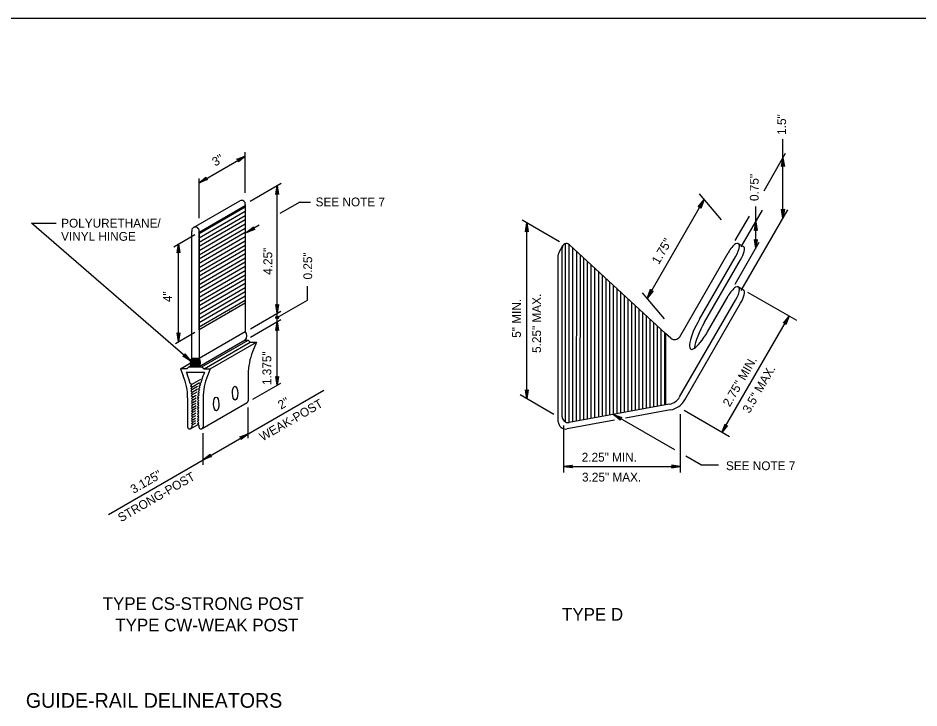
# Model space of a CAD drawing. Extents: x 640253 to 641999, y 298458 to 299646.
# Drawn here: x 640490.1 to 640796.8, y 298801.7 to 299036.6 of the extents above; entities that cross this region are included whole.
import ezdxf

# ---------------------------------------------------------------- set-up
doc = ezdxf.new("R2010")
doc.units = 0
doc.layers.add('1', color=7, linetype='Continuous')
doc.layers.add('2', color=7, linetype='Continuous')

msp = doc.modelspace()

# ---------------------------------------------------------------- linework, layer by layer
at = {"layer": '1'}
msp.add_line((640293.31, 299036.63), (641079.31, 299036.63), dxfattribs=at)
at = {"layer": '2'}
for p, q in [((640750.54, 298968.53), (640750.54, 298995.34)), ((640567.51, 298977.15), (640567.51, 298990.93)), ((640744.09, 298977.84), (640751.44, 298990.57)), ((640551.76, 298980.53), (640567.51, 298989.62)), ((640551.76, 298968.46), (640551.76, 298982)), ((640569.19, 298974.27), (640579.72, 298980.35)), ((640578.36, 298936.09), (640578.36, 298979.57)), ((640704.26, 298941.18), (640723.7, 298974.85)), ((640729.66, 298967.89), (640722.11, 298976.71)), ((640549.88, 298965.29), (640565.62, 298974.38)), ((640551.76, 298963.24), (640567.51, 298972.33)), ((640567.51, 298973.08), (640567.51, 298929.88)), ((640586.04, 298973.92), (640579.26, 298970.05)), ((640586.04, 298973.92), (640589.7, 298973.92)), ((640741.28, 298967.28), (640741.28, 298972.5)), ((640551.76, 298961.8), (640567.51, 298970.89)), ((640551.76, 298960.36), (640567.51, 298969.44)), ((640734.29, 298960.88), (640739.09, 298969.18)), ((640736.28, 298943.84), (640752.15, 298971.31)), ((640736.31, 298958.67), (640743.57, 298971.24)), ((640494.74, 298966.76), (640503.1, 298966.76)), ((640548.82, 298919.89), (640494.74, 298966.76)), ((640551.76, 298958.91), (640567.51, 298968)), ((640551.76, 298957.47), (640567.51, 298966.56)), ((640572.24, 298966.05), (640567.94, 298963.59)), ((640674.43, 298960.44), (640661.77, 298967.76)), ((640663.36, 298907.01), (640663.36, 298966.84)), ((640741.28, 298958.24), (640741.28, 298967.28)), ((640543.17, 298958.76), (640550.37, 298962.92)), ((640549.27, 298920.78), (640549.27, 298963.99)), ((640551.76, 298956.02), (640567.51, 298965.11)), ((640551.76, 298963.99), (640551.76, 298920.78)), ((640551.76, 298963.46), (640551.99, 298963.86)), ((640551.76, 298963.5), (640551.96, 298963.84)), ((640551.76, 298954.58), (640567.51, 298963.67)), ((640551.76, 298953.14), (640567.51, 298962.23)), ((640544.78, 298926.43), (640544.78, 298959.7)), ((640551.76, 298951.7), (640567.51, 298960.78)), ((640551.76, 298950.25), (640567.51, 298959.34)), ((640674.3, 298956.85), (640675.62, 298959.13)), ((640676.55, 298899.06), (640676.56, 298959.77)), ((640677.8, 298898.91), (640677.8, 298959.48)), ((640695.7, 298942.98), (640677.87, 298959.44)), ((640677.9, 298959.42), (640710.55, 298929.26)), ((640734.24, 298946.06), (640742.46, 298960.28)), ((640735.34, 298959.83), (640737.1, 298958.82)), ((640551.76, 298948.81), (640567.51, 298957.9)), ((640551.76, 298947.36), (640567.51, 298956.45)), ((640674.06, 298899.19), (640674.06, 298956.04)), ((640675.38, 298900.87), (640675.38, 298958.32)), ((640679.05, 298899.14), (640679.05, 298958.35)), ((640680.3, 298899.37), (640680.31, 298957.2)), ((640681.55, 298899.6), (640681.56, 298956.04)), ((640715.38, 298928.12), (640731.89, 298956.72)), ((640551.76, 298945.92), (640567.51, 298955.01)), ((640551.76, 298944.48), (640567.51, 298953.57)), ((640682.8, 298899.83), (640682.8, 298954.89)), ((640684.05, 298900.06), (640684.05, 298953.73)), ((640722.09, 298934.05), (640734.39, 298955.34)), ((640723.82, 298933.05), (640736.12, 298954.34)), ((640551.76, 298943.03), (640567.51, 298952.12)), ((640551.76, 298941.59), (640567.51, 298950.68)), ((640685.3, 298900.29), (640685.3, 298952.58)), ((640686.55, 298900.52), (640686.55, 298951.42)), ((640687.8, 298900.75), (640687.8, 298950.27)), ((640551.76, 298940.15), (640567.51, 298949.24)), ((640551.76, 298938.7), (640567.51, 298947.79)), ((640689.05, 298900.98), (640689.05, 298949.12)), ((640690.3, 298901.2), (640690.3, 298947.96)), ((640691.55, 298901.43), (640691.55, 298946.81)), ((640551.76, 298937.26), (640567.51, 298946.35)), ((640551.76, 298935.82), (640567.51, 298944.91)), ((640588.68, 298940.61), (640588.68, 298945.31)), ((640692.8, 298901.66), (640692.8, 298945.65)), ((640694.05, 298901.89), (640694.06, 298944.5)), ((640735.35, 298945.09), (640737.12, 298944.07)), ((640551.76, 298934.37), (640567.51, 298943.46)), ((640551.76, 298932.93), (640567.51, 298942.02)), ((640695.3, 298902.12), (640695.3, 298943.35)), ((640696.55, 298902.35), (640696.55, 298942.19)), ((640697.8, 298902.58), (640697.8, 298941.04)), ((640710.22, 298934.23), (640702.67, 298943.04)), ((640724.85, 298929.79), (640731.87, 298941.95)), ((640755.23, 298933.62), (640738.62, 298943.2)), ((640551.76, 298931.49), (640567.51, 298940.58)), ((640578.36, 298934.65), (640588.68, 298940.61)), ((640699.05, 298902.81), (640699.05, 298939.88)), ((640700.3, 298903.04), (640700.3, 298938.73)), ((640715.35, 298907.59), (640734.39, 298940.55)), ((640717.08, 298906.59), (640736.12, 298939.55)), ((640562.12, 298936.44), (640562.43, 298936.96)), ((640569.22, 298930.82), (640579.61, 298936.81)), ((640578.36, 298933.2), (640578.36, 298936.09)), ((640701.55, 298903.27), (640701.55, 298937.57)), ((640702.8, 298903.5), (640702.8, 298936.42)), ((640704.05, 298903.73), (640704.05, 298935.27)), ((640729.75, 298895.51), (640752.63, 298935.12)), ((640569.22, 298927.93), (640579.61, 298933.93)), ((640578.36, 298911.57), (640578.36, 298933.2)), ((640705.3, 298903.96), (640705.3, 298934.11)), ((640706.55, 298904.19), (640706.55, 298932.96)), ((640707.8, 298904.41), (640707.8, 298931.8)), ((640543.72, 298925.81), (640550.3, 298929.61)), ((640551.76, 298920.78), (640567.51, 298929.88)), ((640709.05, 298904.64), (640709.05, 298930.65)), ((640710.3, 298904.87), (640710.3, 298929.5)), ((640712.37, 298927.59), (640710.55, 298929.26)), ((640710.55, 298929.26), (640710.55, 298904.92)), ((640567.51, 298926.99), (640551.76, 298917.9)), ((640552.74, 298917.9), (640568.49, 298926.99)), ((640553.45, 298917.19), (640569.2, 298926.28)), ((640555.6, 298917.19), (640571.35, 298926.28)), ((640567.51, 298926.99), (640568.49, 298926.99)), ((640568.49, 298926.99), (640569.2, 298926.28)), ((640569.2, 298926.28), (640571.35, 298926.28)), ((640571.35, 298926.28), (640570.01, 298923.02)), ((640548.77, 298919.45), (640550.11, 298920.78)), ((640548.79, 298919.12), (640550.46, 298920.78)), ((640548.84, 298918.82), (640550.81, 298920.78)), ((640548.85, 298919.89), (640549.75, 298920.78)), ((640548.92, 298918.54), (640551.17, 298920.78)), ((640549.01, 298918.28), (640551.52, 298920.78)), ((640549.07, 298920.46), (640549.4, 298920.78)), ((640549.15, 298918.06), (640551.81, 298920.72)), ((640549.27, 298920.78), (640551.76, 298920.78)), ((640549.34, 298917.9), (640551.95, 298920.51)), ((640549.69, 298917.9), (640552.08, 298920.28)), ((640550.04, 298917.9), (640552.16, 298920.01)), ((640550.4, 298917.9), (640552.23, 298919.73)), ((640550.75, 298917.9), (640552.27, 298919.41)), ((640545.43, 298917.19), (640548.77, 298919.11)), ((640547.58, 298917.19), (640545.43, 298917.19)), ((640545.43, 298917.19), (640546.4, 298914.83)), ((640548.29, 298917.9), (640547.58, 298917.19)), ((640548.29, 298917.9), (640549, 298918.31)), ((640548.29, 298917.9), (640552.74, 298917.9)), ((640551.1, 298917.9), (640552.24, 298919.03)), ((640551.46, 298917.9), (640552.13, 298918.57)), ((640551.76, 298917.9), (640551.77, 298917.9)), ((640552.74, 298917.9), (640553.45, 298917.19)), ((640553.45, 298917.19), (640555.6, 298917.19)), ((640555.6, 298917.19), (640554.63, 298914.83)), ((640547.42, 298916.07), (640553.61, 298916.07)), ((640547.42, 298916.07), (640547.68, 298915.43)), ((640549.22, 298911.82), (640552.36, 298913.63)), ((640553.61, 298916.07), (640553.34, 298915.42)), ((640568.51, 298915.36), (640568.51, 298906.3)), ((640549.2, 298911.84), (640548.72, 298912.18)), ((640549.22, 298911.82), (640548.81, 298911.24)), ((640549.25, 298910.94), (640548.81, 298911.24)), ((640549.25, 298910.94), (640548.93, 298910.49)), ((640549.35, 298910.13), (640548.93, 298910.49)), ((640549.35, 298910.13), (640548.96, 298909.68)), ((640549.25, 298910.94), (640551.95, 298912.5)), ((640549.35, 298910.13), (640551.26, 298911.23)), ((640549.45, 298909.26), (640551.29, 298910.32)), ((640551.54, 298910.33), (640552.06, 298910.78)), ((640551.54, 298910.33), (640551.93, 298909.88)), ((640551.71, 298911.27), (640552.21, 298911.62)), ((640551.71, 298911.27), (640552.06, 298910.78)), ((640551.86, 298912.11), (640552.38, 298912.47)), ((640551.86, 298912.11), (640552.21, 298911.62)), ((640570.1, 298906.8), (640579.61, 298912.29)), ((640520.9, 298867.59), (640594.28, 298909.95)), ((640547.88, 298907.26), (640547.88, 298897.42)), ((640549.45, 298909.26), (640548.96, 298909.68)), ((640549.45, 298909.26), (640549.06, 298908.81)), ((640549.52, 298908.41), (640549.06, 298908.81)), ((640549.52, 298908.41), (640549.13, 298907.96)), ((640549.61, 298907.48), (640549.13, 298907.96)), ((640549.61, 298907.48), (640549.19, 298907.06)), ((640549.65, 298906.6), (640549.19, 298907.06)), ((640549.52, 298908.41), (640551.16, 298909.36)), ((640549.61, 298907.48), (640550.83, 298908.18)), ((640549.65, 298906.6), (640550.76, 298907.25)), ((640551.24, 298906.81), (640551.7, 298907.26)), ((640551.28, 298907.68), (640551.76, 298908.16)), ((640551.28, 298907.68), (640551.7, 298907.26)), ((640551.37, 298908.61), (640551.83, 298909.02)), ((640551.37, 298908.61), (640551.76, 298908.17)), ((640551.44, 298909.47), (640551.93, 298909.88)), ((640551.44, 298909.47), (640551.83, 298909.02)), ((640553.15, 298907.26), (640553.15, 298897.42)), ((640672.59, 298901.68), (640661.07, 298908.33)), ((640549.65, 298906.6), (640549.23, 298906.18)), ((640549.66, 298905.75), (640549.23, 298906.18)), ((640549.66, 298905.75), (640549.24, 298905.33)), ((640549.66, 298904.91), (640549.24, 298905.33)), ((640549.66, 298904.91), (640549.24, 298904.49)), ((640549.66, 298904.07), (640549.24, 298904.49)), ((640549.66, 298904.07), (640549.24, 298903.65)), ((640549.66, 298905.75), (640550.73, 298906.37)), ((640549.66, 298904.91), (640550.75, 298905.54)), ((640549.66, 298904.07), (640550.73, 298904.69)), ((640549.66, 298903.23), (640550.73, 298903.85)), ((640551.23, 298905.96), (640551.66, 298906.39)), ((640551.23, 298905.96), (640551.65, 298905.53)), ((640551.23, 298905.12), (640551.65, 298905.53)), ((640551.23, 298905.12), (640551.65, 298904.7)), ((640551.23, 298904.27), (640551.65, 298904.7)), ((640551.23, 298904.27), (640551.65, 298903.86)), ((640551.23, 298903.43), (640551.65, 298903.86)), ((640551.24, 298906.81), (640551.66, 298906.39)), ((640552.8, 298896.81), (640568.16, 298905.68)), ((640568.51, 298893.62), (640568.51, 298904.04)), ((640710.55, 298904.92), (640677.74, 298898.9)), ((640711.92, 298905.17), (640710.55, 298904.92)), ((640549.66, 298903.23), (640549.24, 298903.65)), ((640549.66, 298903.23), (640549.24, 298902.81)), ((640549.66, 298902.39), (640549.24, 298902.81)), ((640549.66, 298902.39), (640549.24, 298901.97)), ((640549.66, 298901.55), (640549.24, 298901.97)), ((640549.66, 298901.55), (640549.24, 298901.13)), ((640549.66, 298900.71), (640549.24, 298901.13)), ((640549.66, 298902.39), (640550.62, 298902.95)), ((640549.66, 298901.55), (640550.7, 298902.15)), ((640549.66, 298900.71), (640550.71, 298901.32)), ((640551.23, 298903.43), (640551.65, 298903.02)), ((640551.23, 298902.6), (640551.65, 298903.02)), ((640551.23, 298902.6), (640551.65, 298902.17)), ((640551.23, 298901.76), (640551.65, 298902.17)), ((640551.23, 298901.76), (640551.65, 298901.33)), ((640551.23, 298900.92), (640551.65, 298901.33)), ((640551.23, 298900.92), (640551.65, 298900.5)), ((640713.78, 298889.55), (640692.81, 298901.66)), ((640712.28, 298903.2), (640696.92, 298900.39)), ((640715.61, 298881.93), (640715.62, 298901.7)), ((640732.35, 298894.01), (640716.86, 298902.95)), ((640548.95, 298896.81), (640551.25, 298898.14)), ((640549.66, 298900.71), (640549.24, 298900.29)), ((640549.66, 298899.87), (640549.24, 298900.29)), ((640549.66, 298899.87), (640549.24, 298899.45)), ((640549.66, 298899.03), (640549.24, 298899.45)), ((640549.66, 298899.03), (640549.24, 298898.61)), ((640549.66, 298898.19), (640549.24, 298898.61)), ((640549.3, 298897.83), (640549.66, 298898.19)), ((640549.3, 298897.83), (640549.3, 298897.42)), ((640549.66, 298899.87), (640550.52, 298900.36)), ((640549.66, 298899.03), (640550.62, 298899.58)), ((640549.66, 298898.19), (640550.71, 298898.8)), ((640551.23, 298900.07), (640551.65, 298900.5)), ((640551.23, 298900.07), (640551.65, 298899.66)), ((640551.23, 298899.23), (640551.65, 298899.66)), ((640551.23, 298899.23), (640551.65, 298898.82)), ((640551.23, 298898.4), (640551.65, 298898.82)), ((640551.23, 298898.4), (640551.73, 298897.89)), ((640551.73, 298897.89), (640551.73, 298897.42)), ((640675.94, 298881.93), (640675.94, 298897.93)), ((640693.24, 298899.71), (640677.02, 298896.73)), ((640553.15, 298884.45), (640553.15, 298895.29)), ((640722.62, 298884.45), (640717.48, 298887.42)), ((640675.94, 298883.95), (640715.61, 298883.95)), ((640722.62, 298884.45), (640728.59, 298884.45))]:
    msp.add_line(p, q, dxfattribs=at)
for points in [[(640564.86, 298988.51), (640565.05, 298988.38), (640567.51, 298989.62), (640564.86, 298988.51), (640564.67, 298988.54), (640567.51, 298989.62), (640565.2, 298988.13), (640565.21, 298987.91), (640567.51, 298989.62), (640565.15, 298987.71), (640565.21, 298987.91)], [(640750.18, 298986.16), (640750.39, 298986.27), (640750.54, 298989.02), (640750.18, 298986.16), (640750.06, 298986.02), (640750.54, 298989.02), (640750.68, 298986.27), (640750.88, 298986.17), (640750.54, 298989.02), (640751.02, 298986.02), (640750.88, 298986.17)], [(640554.41, 298981.65), (640554.22, 298981.78), (640551.76, 298980.53), (640554.41, 298981.65), (640554.6, 298981.62), (640551.76, 298980.53), (640554.07, 298982.02), (640554.06, 298982.25), (640551.76, 298980.53), (640554.12, 298982.45), (640554.06, 298982.25)], [(640578, 298976.71), (640578.21, 298976.82), (640578.36, 298979.57), (640578, 298976.71), (640577.87, 298976.57), (640578.36, 298979.57), (640578.49, 298976.82), (640578.7, 298976.72), (640578.36, 298979.57), (640578.83, 298976.57), (640578.7, 298976.72)], [(640721.82, 298972.37), (640722.07, 298972.35), (640723.7, 298974.85), (640721.82, 298972.37), (640721.63, 298972.3), (640723.7, 298974.85), (640722.34, 298972.2), (640722.48, 298972), (640723.7, 298974.85), (640722.53, 298971.78), (640722.48, 298972)], [(640750.9, 298971.38), (640750.69, 298971.27), (640750.54, 298968.53), (640750.9, 298971.38), (640751.02, 298971.53), (640750.54, 298968.53), (640750.4, 298971.27), (640750.2, 298971.37), (640750.54, 298968.53), (640750.06, 298971.53), (640750.2, 298971.37)], [(640570.6, 298964.7), (640570.4, 298964.82), (640567.94, 298963.59), (640570.6, 298964.7), (640570.79, 298964.66), (640567.94, 298963.59), (640570.26, 298965.07), (640570.25, 298965.3), (640567.94, 298963.59), (640570.31, 298965.49), (640570.25, 298965.3)], [(640663, 298963.99), (640663.21, 298964.09), (640663.36, 298966.84), (640663, 298963.99), (640662.88, 298963.84), (640663.36, 298966.84), (640663.49, 298964.1), (640663.7, 298963.99), (640663.36, 298966.84), (640663.83, 298963.84), (640663.7, 298963.99)], [(640740.92, 298964.43), (640741.13, 298964.53), (640741.28, 298967.28), (640740.92, 298964.43), (640740.8, 298964.28), (640741.28, 298967.28), (640741.42, 298964.53), (640741.62, 298964.43), (640741.28, 298967.28), (640741.76, 298964.28), (640741.62, 298964.43)], [(640544.43, 298956.84), (640544.63, 298956.95), (640544.78, 298959.7), (640544.43, 298956.84), (640544.3, 298956.7), (640544.78, 298959.7), (640544.92, 298956.95), (640545.12, 298956.85), (640544.78, 298959.7), (640545.26, 298956.7), (640545.12, 298956.85)], [(640741.64, 298961.1), (640741.43, 298960.99), (640741.28, 298958.24), (640741.64, 298961.1), (640741.76, 298961.24), (640741.28, 298958.24), (640741.15, 298960.99), (640740.94, 298961.09), (640741.28, 298958.24), (640740.81, 298961.24), (640740.94, 298961.09)], [(640706.14, 298943.66), (640705.89, 298943.67), (640704.26, 298941.18), (640706.14, 298943.66), (640706.34, 298943.73), (640704.26, 298941.18), (640705.62, 298943.83), (640705.48, 298944.03), (640704.26, 298941.18), (640705.44, 298944.25), (640705.48, 298944.03)], [(640706.14, 298943.66), (640705.89, 298943.67), (640704.26, 298941.18), (640706.14, 298943.66), (640706.34, 298943.73), (640704.26, 298941.18), (640705.62, 298943.83), (640705.48, 298944.03), (640704.26, 298941.18), (640705.44, 298944.25), (640705.48, 298944.03)], [(640578.72, 298938.95), (640578.51, 298938.84), (640578.36, 298936.09), (640578.72, 298938.95), (640578.84, 298939.09), (640578.36, 298936.09), (640578.22, 298938.84), (640578.02, 298938.94), (640578.36, 298936.09), (640577.88, 298939.09), (640578.02, 298938.94)], [(640750.89, 298932.82), (640751.12, 298932.81), (640752.63, 298935.12), (640750.89, 298932.82), (640750.71, 298932.76), (640752.63, 298935.12), (640751.37, 298932.67), (640751.5, 298932.48), (640752.63, 298935.12), (640751.54, 298932.28), (640751.5, 298932.48)], [(640578, 298930.35), (640578.21, 298930.46), (640578.36, 298933.2), (640578, 298930.35), (640577.87, 298930.2), (640578.36, 298933.2), (640578.49, 298930.46), (640578.7, 298930.36), (640578.36, 298933.2), (640578.83, 298930.2), (640578.7, 298930.36)], [(640545.14, 298929.28), (640544.94, 298929.18), (640544.78, 298926.43), (640545.14, 298929.28), (640545.27, 298929.43), (640544.78, 298926.43), (640544.65, 298929.17), (640544.45, 298929.27), (640544.78, 298926.43), (640544.31, 298929.43), (640544.45, 298929.27)], [(640546.93, 298922.05), (640546.87, 298921.83), (640548.82, 298919.89), (640546.93, 298922.05), (640546.9, 298922.25), (640548.82, 298919.89), (640546.68, 298921.61), (640546.47, 298921.53), (640548.82, 298919.89), (640546.26, 298921.53), (640546.47, 298921.53)], [(640578.72, 298914.42), (640578.51, 298914.32), (640578.36, 298911.57), (640578.72, 298914.42), (640578.84, 298914.57), (640578.36, 298911.57), (640578.22, 298914.31), (640578.02, 298914.41), (640578.36, 298911.57), (640577.88, 298914.57), (640578.02, 298914.41)], [(640663.72, 298909.86), (640663.51, 298909.75), (640663.36, 298907.01), (640663.72, 298909.86), (640663.84, 298910.01), (640663.36, 298907.01), (640663.22, 298909.75), (640663.02, 298909.85), (640663.36, 298907.01), (640662.88, 298910.01), (640663.02, 298909.85)], [(640695.1, 298899.93), (640695.11, 298900.16), (640692.81, 298901.66), (640695.1, 298899.93), (640695.16, 298899.75), (640692.81, 298901.66), (640695.25, 298900.41), (640695.44, 298900.54), (640692.81, 298901.66), (640695.64, 298900.58), (640695.44, 298900.54)], [(640731.49, 298897.8), (640731.26, 298897.81), (640729.75, 298895.51), (640731.49, 298897.8), (640731.67, 298897.86), (640729.75, 298895.51), (640731.01, 298897.95), (640730.88, 298898.14), (640729.75, 298895.51), (640730.84, 298898.34), (640730.88, 298898.14)], [(640565.86, 298893.96), (640566.06, 298893.83), (640568.51, 298895.07), (640565.86, 298893.96), (640565.67, 298893.99), (640568.51, 298895.07), (640566.2, 298893.58), (640566.22, 298893.36), (640568.51, 298895.07), (640566.15, 298893.16), (640566.22, 298893.36)], [(640555.8, 298887.32), (640555.6, 298887.45), (640553.15, 298886.21), (640555.8, 298887.32), (640555.99, 298887.29), (640553.15, 298886.21), (640555.46, 298887.7), (640555.44, 298887.92), (640553.15, 298886.21), (640555.51, 298888.12), (640555.44, 298887.92)], [(640678.79, 298883.6), (640678.68, 298883.8), (640675.94, 298883.95), (640678.79, 298883.6), (640678.94, 298883.47), (640675.94, 298883.95), (640678.68, 298884.09), (640678.78, 298884.29), (640675.94, 298883.95), (640678.94, 298884.43), (640678.78, 298884.29)], [(640712.76, 298883.6), (640712.87, 298883.8), (640715.61, 298883.95), (640712.76, 298883.6), (640712.61, 298883.47), (640715.61, 298883.95), (640712.87, 298884.09), (640712.77, 298884.29), (640715.61, 298883.95), (640712.61, 298884.43), (640712.77, 298884.29)]]:
    msp.add_lwpolyline(points, dxfattribs=at)
msp.add_lwpolyline([(640551.76, 298930.46), (640551.76, 298963.72), (640567.51, 298972.81), (640567.51, 298939.55)], close=True, dxfattribs=at)
msp.add_circle((640578.36, 298934.65), 0.444, dxfattribs=at)
for centre, radius, start, end in [((640566.26, 298973.28), 1.26, 350.9133, 119.9792), ((640550.51, 298964.19), 1.26, 350.9133, 189.0867), ((640676.88, 298958.32), 1.5, 47.2827, 180.0033), ((640675.56, 298956.04), 1.5, 147.1819, 180.0033), ((640565.73, 298928.43), 2.29, 320.9923, 39.0623), ((640713.65, 298929.12), 2, 230.2615, 329.996), ((640588.76, 298915.36), 20.25, 157.7877, 180), ((640551.05, 298919.34), 2.29, 140.9377, 219.0623), ((640549.98, 298919.34), 2.29, 320.9923, 39.0623), ((640527.88, 298907.26), 20, 0, 22.2204), ((640527.55, 298907.2), 21.75, 13.2354, 22.2267), ((640573.48, 298907.2), 21.75, 157.7963, 165.9872), ((640573.15, 298907.26), 20, 157.7833, 180), ((640711.02, 298910.09), 5, 280.3803, 329.996), ((640567.8, 298906.3), 0.709, 300.0103, 0), ((640711.02, 298910.09), 7, 280.3899, 329.996), ((640677.38, 298900.87), 2, 180.0098, 280.3902), ((640676.56, 298899.19), 2.5, 179.9993, 280.3971), ((640548.59, 298897.42), 0.709, 180, 0), ((640552.44, 298897.42), 0.709, 180.005, 0)]:
    msp.add_arc(centre, radius, start, end, dxfattribs=at)
for centre, major_axis, ratio, start_param, end_param in [((640733.31, 298956.32), (2.03, 3.52), 0.351581, 4.636261, 7.943286), ((640735.04, 298955.32), (2.03, 3.52), 0.351581, 4.636261, 6.257684), ((640733.3, 298941.54), (2.05, 3.55), 0.351581, 4.636261, 7.943286), ((640735.03, 298940.54), (2.05, 3.55), 0.351581, 4.636261, 6.250381), ((640723.43, 298931.84), (4.28, 7.98), 0.247592, 1.425353, 4.587399), ((640725.16, 298930.84), (4.28, 7.98), 0.247592, 1.425353, 2.620687)]:
    msp.add_ellipse(centre, major_axis=major_axis, ratio=ratio, start_param=start_param, end_param=end_param, dxfattribs=at)
for centre in [(640564.02, 298908.91), (640557.63, 298905.22)]:
    msp.add_ellipse(centre, major_axis=(0.05, -2.36), ratio=0.379302, dxfattribs=at)

# ---------------------------------------------------------------- texts
for s, rotation, p in [('1.5" ', 89.996, (640751.59, 298996.85)), ('3"', 30, (640557.26, 298986.03)), ('0.75" ', 89.996, (640742.26, 298974.32)), ('1.75" ', 59.996, (640708.26, 298952.5)), ('4.25"', 90, (640576.66, 298949.2)), ('0.25"', 90, (640590.26, 298947.61)), ('4"', 90, (640542.54, 298939.92)), ('5.25" MAX.', 89.996, (640668.18, 298922.59)), ('5" MIN.', 89.996, (640661.33, 298927.76)), ('1.375"', 90, (640576.36, 298911.65)), ('2.75" MIN.', 59.996, (640732.43, 298904.03)), ('3.5" MAX.', 59.996, (640739.14, 298901.8)), ('WEAK-POST', 30, (640573.38, 298892.44)), ('2"', 30, (640579.68, 298903.27)), ('3.125"', 30, (640529.47, 298874.57)), ('STRONG-POST', 30, (640525.22, 298864.91))]:
    msp.add_text(s, height=3, rotation=rotation, dxfattribs=at).set_placement(p)
for s, height, p in [('SEE NOTE 7', 3, (640591.44, 298972.5)), ('POLYURETHANE/', 3, (640504.82, 298965.28)), ('VINYL HINGE  ', 3, (640504.8, 298960.78)), ('2.25" MIN.', 3, (640682.03, 298885.58)), ('SEE NOTE 7', 3, (640731.13, 298882.68)), ('3.25" MAX.', 3, (640682.13, 298878.81)), ('TYPE CS-STRONG POST', 4.3, (640518.97, 298835.09)), ('TYPE D', 4.3, (640675.35, 298831.44)), ('TYPE CW-WEAK POST', 4.3, (640523.27, 298827.79)), ('GUIDE-RAIL DELINEATORS', 5, (640492.79, 298801.78))]:
    msp.add_text(s, height=height, dxfattribs=at).set_placement(p)

doc.saveas('drawing.dxf')
